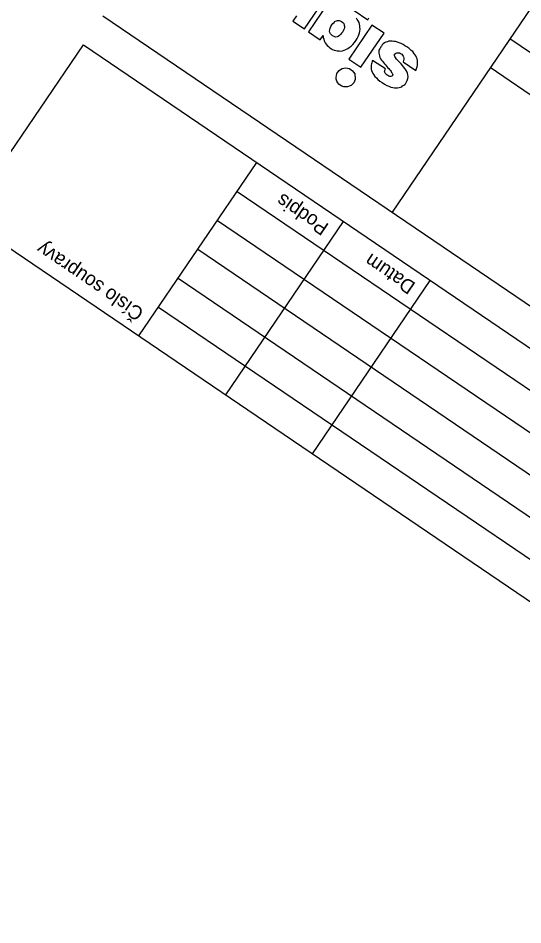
# Model space of a CAD drawing. Extents: x -620450 to -619936, y -1122925 to -1122443.
# Drawn here: x -620394.6 to -620358.5, y -1122676.5 to -1122611.6 of the extents above; entities that cross this region are included whole.
import ezdxf

# ---------------------------------------------------------------- set-up
doc = ezdxf.new("R2010")
doc.units = 0
for name, color, linetype in [('060603_ROZVODY_NN', 7, 'Continuous'), ('BODY POPIS', 7, 'Continuous'), ('Vrstva 3', 7, 'Continuous'), ('Vrstva 4', 7, 'Continuous')]:
    doc.layers.add(name, color=color, linetype=linetype)

msp = doc.modelspace()

# ---------------------------------------------------------------- linework, layer by layer
at = {"layer": '060603_ROZVODY_NN'}
msp.add_lwpolyline([(-620371.578, -1122616.388), (-620371.681, -1122616.307), (-620371.748, -1122616.206), (-620371.804, -1122616.089), (-620371.856, -1122615.951), (-620371.861, -1122615.825), (-620371.839, -1122615.693), (-620371.804, -1122615.559), (-620371.738, -1122615.445), (-620371.657, -1122615.342), (-620371.54, -1122615.253), (-620371.426, -1122615.184), (-620371.317, -1122615.156), (-620371.159, -1122615.14), (-620371.04, -1122615.164), (-620370.921, -1122615.188), (-620370.808, -1122615.254), (-620370.689, -1122615.346), (-620370.615, -1122615.452), (-620370.533, -1122615.564), (-620370.514, -1122615.702), (-620370.492, -1122615.818), (-620370.491, -1122615.966), (-620370.538, -1122616.102), (-620370.589, -1122616.226), (-620370.685, -1122616.319), (-620370.789, -1122616.405), (-620370.927, -1122616.459), (-620371.054, -1122616.496), (-620371.178, -1122616.514), (-620371.323, -1122616.494), (-620371.449, -1122616.465), (-620371.578, -1122616.388)], dxfattribs=at)
at = {"layer": 'Vrstva 3'}
for p, q in [((-620343.989, -1122590.312), (-620367.866, -1122625.47)), ((-620388.548, -1122611.425), (-620314.095, -1122661.989)), ((-620305.667, -1122649.58), (-620359.439, -1122613.062)), ((-620398.38, -1122625.902), (-620389.952, -1122613.493)), ((-620389.952, -1122613.493), (-620315.499, -1122664.057)), ((-620307.072, -1122651.648), (-620360.844, -1122615.13)), ((-620385.971, -1122634.329), (-620377.543, -1122621.92)), ((-620378.948, -1122623.989), (-620316.904, -1122666.125)), ((-620398.38, -1122625.902), (-620323.926, -1122676.466)), ((-620380.353, -1122626.057), (-620318.308, -1122668.193)), ((-620379.766, -1122638.543), (-620371.339, -1122626.134)), ((-620381.757, -1122628.125), (-620319.713, -1122670.261)), ((-620383.162, -1122630.193), (-620321.117, -1122672.33)), ((-620373.562, -1122642.757), (-620365.135, -1122630.348)), ((-620384.566, -1122632.261), (-620322.522, -1122674.398))]:
    msp.add_line(p, q, dxfattribs=at)
at = {"layer": 'Vrstva 4'}
for points in [[(-620374.128, -1122612.356), (-620372.477, -1122609.925)], [(-620372.47, -1122610.562), (-620373.833, -1122612.568), (-620372.999, -1122613.134)], [(-620370.573, -1122611.039), (-620369.593, -1122611.704), (-620369.532, -1122611.565)], [(-620374.697, -1122611.417), (-620374.954, -1122611.796), (-620374.128, -1122612.356)], [(-620372.999, -1122613.134), (-620372.795, -1122612.833), (-620372.783, -1122612.965), (-620372.753, -1122613.087), (-620372.715, -1122613.214), (-620372.657, -1122613.344), (-620372.588, -1122613.459), (-620372.511, -1122613.545), (-620372.421, -1122613.628), (-620372.311, -1122613.714), (-620372.198, -1122613.78), (-620372.115, -1122613.825), (-620371.996, -1122613.883), (-620371.893, -1122613.897), (-620371.785, -1122613.936), (-620371.658, -1122613.932), (-620371.534, -1122613.949), (-620371.405, -1122613.924), (-620371.29, -1122613.889), (-620371.16, -1122613.831), (-620371.038, -1122613.767), (-620370.932, -1122613.693), (-620370.796, -1122613.593), (-620370.671, -1122613.475), (-620370.551, -1122613.331), (-620370.441, -1122613.169), (-620370.352, -1122613.038), (-620370.288, -1122612.912), (-620370.246, -1122612.783), (-620370.198, -1122612.646), (-620370.169, -1122612.52), (-620370.154, -1122612.382), (-620370.166, -1122612.25), (-620370.176, -1122612.131), (-620370.198, -1122612.015), (-620370.226, -1122611.906), (-620370.281, -1122611.789), (-620370.348, -1122611.688), (-620370.414, -1122611.586)], [(-620372.112, -1122612.857), (-620372.186, -1122612.784), (-620372.256, -1122612.703), (-620372.307, -1122612.612), (-620372.332, -1122612.516), (-620372.318, -1122612.413), (-620372.291, -1122612.307), (-620372.248, -1122612.178), (-620372.17, -1122612.062), (-620372.102, -1122611.962), (-620372.008, -1122611.89), (-620371.922, -1122611.813), (-620371.836, -1122611.771), (-620371.758, -1122611.755), (-620371.652, -1122611.749), (-620371.567, -1122611.773), (-620371.469, -1122611.828), (-620371.382, -1122611.898), (-620371.32, -1122611.974), (-620371.28, -1122612.08), (-620371.26, -1122612.15), (-620371.274, -1122612.254), (-620371.282, -1122612.35), (-620371.33, -1122612.453), (-620371.39, -1122612.558), (-620371.471, -1122612.661), (-620371.555, -1122612.751), (-620371.633, -1122612.833), (-620371.722, -1122612.897), (-620371.797, -1122612.925), (-620371.908, -1122612.939), (-620372.001, -1122612.91), (-620372.112, -1122612.857)], [(-620370.085, -1122615.102), (-620368.434, -1122612.671), (-620369.298, -1122612.085), (-620370.949, -1122614.516), (-620370.085, -1122615.102)], [(-620368.342, -1122615.226), (-620369.252, -1122614.608), (-620369.282, -1122614.7), (-620369.313, -1122614.781), (-620369.337, -1122614.865), (-620369.354, -1122614.956), (-620369.357, -1122615.044), (-620369.358, -1122615.145), (-620369.354, -1122615.238), (-620369.331, -1122615.355), (-620369.288, -1122615.44), (-620369.235, -1122615.544), (-620369.168, -1122615.646), (-620369.086, -1122615.758), (-620368.986, -1122615.86), (-620368.871, -1122615.972), (-620368.735, -1122616.087), (-620368.578, -1122616.204), (-620368.411, -1122616.307), (-620368.246, -1122616.396), (-620368.094, -1122616.455), (-620367.947, -1122616.52), (-620367.812, -1122616.555), (-620367.689, -1122616.572), (-620367.575, -1122616.57), (-620367.461, -1122616.569), (-620367.349, -1122616.554), (-620367.261, -1122616.524), (-620367.173, -1122616.493), (-620367.103, -1122616.44), (-620367.019, -1122616.383), (-620366.957, -1122616.325), (-620366.905, -1122616.281), (-620366.847, -1122616.196), (-620366.786, -1122616.057), (-620366.741, -1122615.907), (-620366.717, -1122615.788), (-620366.726, -1122615.636), (-620366.759, -1122615.534), (-620366.796, -1122615.407), (-620366.865, -1122615.293), (-620366.952, -1122615.189), (-620367.034, -1122615.077), (-620367.121, -1122614.973), (-620367.208, -1122614.868), (-620367.295, -1122614.764), (-620367.393, -1122614.675), (-620367.475, -1122614.597), (-620367.552, -1122614.511), (-620367.611, -1122614.414), (-620367.674, -1122614.326), (-620367.692, -1122614.269), (-620367.697, -1122614.209), (-620367.678, -1122614.166), (-620367.615, -1122614.107), (-620367.572, -1122614.092), (-620367.53, -1122614.064), (-620367.463, -1122614.064), (-620367.388, -1122614.07), (-620367.339, -1122614.081), (-620367.274, -1122614.102), (-620367.22, -1122614.139), (-620367.166, -1122614.175), (-620367.115, -1122614.233), (-620367.061, -1122614.303), (-620367.038, -1122614.352), (-620367.021, -1122614.443), (-620367.014, -1122614.515), (-620367.035, -1122614.613), (-620367.075, -1122614.722), (-620366.172, -1122615.335), (-620366.104, -1122615.201), (-620366.061, -1122615.072), (-620366.037, -1122614.953), (-620366.031, -1122614.845), (-620366.032, -1122614.731), (-620366.047, -1122614.619), (-620366.069, -1122614.503), (-620366.11, -1122614.397), (-620366.171, -1122614.287), (-620366.232, -1122614.178), (-620366.304, -1122614.084), (-620366.383, -1122613.986), (-620366.494, -1122613.899), (-620366.578, -1122613.808), (-620366.673, -1122613.732), (-620366.804, -1122613.643), (-620366.941, -1122613.562), (-620367.072, -1122613.472), (-620367.211, -1122613.412), (-620367.35, -1122613.351), (-620367.482, -1122613.296), (-620367.609, -1122613.266), (-620367.745, -1122613.252), (-620367.857, -1122613.233), (-620367.978, -1122613.229), (-620368.102, -1122613.246), (-620368.198, -1122613.271), (-620368.3, -1122613.304), (-620368.398, -1122613.35), (-620368.492, -1122613.421), (-620368.563, -1122613.509), (-620368.626, -1122613.601), (-620368.641, -1122613.624), (-620368.657, -1122613.647), (-620368.673, -1122613.671), (-620368.689, -1122613.694), (-620368.709, -1122613.725), (-620368.725, -1122613.748), (-620368.736, -1122613.763), (-620368.746, -1122613.779), (-620368.806, -1122613.884), (-620368.82, -1122613.988), (-620368.819, -1122614.102), (-620368.794, -1122614.198), (-620368.769, -1122614.294), (-620368.733, -1122614.408), (-620368.69, -1122614.493), (-620368.619, -1122614.587), (-620368.554, -1122614.676), (-620368.483, -1122614.77), (-620368.411, -1122614.863), (-620368.337, -1122614.936), (-620368.252, -1122615.028), (-620368.183, -1122615.108), (-620368.101, -1122615.187), (-620368.039, -1122615.262), (-620367.983, -1122615.345), (-620367.924, -1122615.408), (-620367.891, -1122615.476), (-620367.848, -1122615.528), (-620367.833, -1122615.572), (-620367.807, -1122615.634), (-620367.808, -1122615.668), (-620367.828, -1122615.698), (-620367.85, -1122615.729), (-620367.886, -1122615.75), (-620367.938, -1122615.76), (-620367.979, -1122615.754), (-620368.031, -1122615.764), (-620368.085, -1122615.728), (-620368.157, -1122615.701), (-620368.211, -1122615.664), (-620368.273, -1122615.622), (-620368.317, -1122615.57), (-620368.357, -1122615.531), (-620368.388, -1122615.476), (-620368.393, -1122615.417), (-620368.382, -1122615.368), (-620368.382, -1122615.301), (-620368.342, -1122615.226)]]:
    msp.add_lwpolyline(points, dxfattribs=at)

# ---------------------------------------------------------------- texts
at = {"layer": 'BODY POPIS'}
for s, p in [('Podpis', (-620372.319, -1122626.375)), ('Číslo soupravy', (-620385.546, -1122632.502)), ('Datum', (-620366.114, -1122630.589))]:
    msp.add_text(s, height=1, rotation=145.81812, dxfattribs=at).set_placement(p)

doc.saveas('drawing.dxf')
